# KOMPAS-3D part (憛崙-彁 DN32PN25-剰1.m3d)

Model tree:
1. Объединить компоненты:1  (labels: СЕНС-ПР DN32PN25-ДП1)

Referenced files in D:\Савин\!СЕНСОР\3D для заказчика\!Новый перечень\СЕНС-ПР\3. СЕНС-ПР-ДП\DN32\: СЕНС-ПР DN32PN25-ДП1.a3d
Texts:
  СЕНС-ПР DN32PN25-ДП1
  ООО НПП Сенсор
